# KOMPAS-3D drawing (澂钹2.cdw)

Views: Вид 1
Referenced files in D:\Проекты\2019\июнь\Autor24\4102158_21_2019\: Эпюр1.cdw
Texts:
  Вариант №5
  Эпюр №2
  Лукьянов А.С.
  Штриховая 1.5х1.5
  Стили документа
  Вариант №5-
Dimensions and other numbers on the sheet: 1; 2; 2 1 2; 1 1 2; 2 1 1; 1 1 1; 1:1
